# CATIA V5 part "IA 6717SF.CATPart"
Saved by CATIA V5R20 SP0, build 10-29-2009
Part number: IA 6717SF
Revision: ANY
Definition: UNKNOWN
Nomenclature: IA 6717SF
Source: Unknown
Bounding box of the stored display mesh (mm): x -3.35 to 3.35, y -7.95 to 9.02, z -3.186 to 3.186
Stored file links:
  C:\Users\Utente\Desktop\IO LAVORO\3D X SITO CF\CUMSA\3D files IA\IA 6717SF\IA 6717SF.CATPart
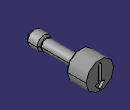
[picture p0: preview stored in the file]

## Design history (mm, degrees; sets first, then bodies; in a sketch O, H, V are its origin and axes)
Body1 "Cortar-Extruir2" (main body)
  Solid1: solid without history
